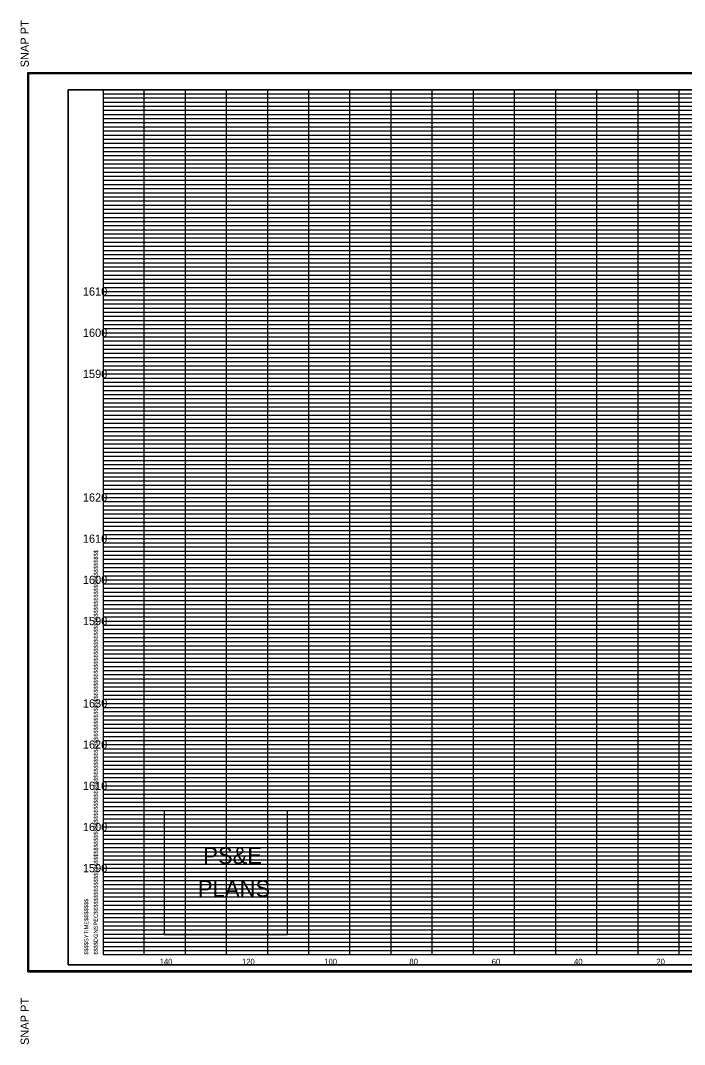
# Model space of a CAD drawing. Extents: x 980 to 1324, y 978 to 1497.
# Drawn here: x 979.9 to 1141.3, y 978.2 to 1226.8 of the extents above; entities that cross this region are included whole.
import ezdxf

# ---------------------------------------------------------------- set-up
doc = ezdxf.new("R2010")
doc.units = 0
for name, color, linetype in [('DESIGN - SHEET - Corner Text', 7, 'Continuous'), ('DESIGN - SHEET - Light Grid', 7, 'Continuous'), ('DESIGN - SHEET - Linework', 7, 'Continuous'), ('DESIGN - SHEET - Plot Shape', 7, 'Continuous'), ('DESIGN - TYPICAL - Text', 7, 'Continuous')]:
    doc.layers.add(name, color=color, linetype=linetype)

# ---------------------------------------------------------------- blocks, each defined once
blk = doc.blocks.new('XSTSHT')
at = {"layer": 'DESIGN - SHEET - Light Grid'}
for p, q in [((0, 20.9), (8, 20.9)), ((8, 20.9), (16, 20.9)), ((0, 20.8), (8, 20.8)), ((0, 20.7), (8, 20.7)), ((8, 20.8), (16, 20.8)), ((8, 20.7), (16, 20.7)), ((0, 20.6), (8, 20.6)), ((0, 20.5), (8, 20.5)), ((0, 20.4), (8, 20.4)), ((8, 20.6), (16, 20.6)), ((8, 20.5), (16, 20.5)), ((8, 20.4), (16, 20.4)), ((0, 20.3), (8, 20.3)), ((0, 20.2), (8, 20.2)), ((8, 20.3), (16, 20.3)), ((8, 20.2), (16, 20.2)), ((0, 20.1), (8, 20.1)), ((0, 19.9), (8, 19.9)), ((8, 20.1), (16, 20.1)), ((8, 19.9), (16, 19.9)), ((0, 19.8), (8, 19.8)), ((0, 19.7), (8, 19.7)), ((8, 19.8), (16, 19.8)), ((8, 19.7), (16, 19.7)), ((0, 19.6), (8, 19.6)), ((0, 19.5), (8, 19.5)), ((0, 19.4), (8, 19.4)), ((8, 19.6), (16, 19.6)), ((8, 19.5), (16, 19.5)), ((8, 19.4), (16, 19.4)), ((0, 19.3), (8, 19.3)), ((0, 19.2), (8, 19.2)), ((8, 19.3), (16, 19.3)), ((8, 19.2), (16, 19.2)), ((0, 19.1), (8, 19.1)), ((0, 18.9), (8, 18.9)), ((8, 19.1), (16, 19.1)), ((8, 18.9), (16, 18.9)), ((0, 18.8), (8, 18.8)), ((0, 18.7), (8, 18.7)), ((8, 18.8), (16, 18.8)), ((8, 18.7), (16, 18.7)), ((0, 18.6), (8, 18.6)), ((0, 18.5), (8, 18.5)), ((0, 18.4), (8, 18.4)), ((8, 18.6), (16, 18.6)), ((8, 18.5), (16, 18.5)), ((8, 18.4), (16, 18.4)), ((0, 18.3), (8, 18.3)), ((0, 18.2), (8, 18.2)), ((8, 18.3), (16, 18.3)), ((8, 18.2), (16, 18.2)), ((0, 18.1), (8, 18.1)), ((8, 18.1), (16, 18.1)), ((0, 17.9), (8, 17.9)), ((0, 17.8), (8, 17.8)), ((0, 17.7), (8, 17.7)), ((8, 17.9), (16, 17.9)), ((8, 17.8), (16, 17.8)), ((8, 17.7), (16, 17.7)), ((0, 17.6), (8, 17.6)), ((0, 17.5), (8, 17.5)), ((8, 17.6), (16, 17.6)), ((8, 17.5), (16, 17.5)), ((0, 17.4), (8, 17.4)), ((0, 17.3), (8, 17.3)), ((0, 17.2), (8, 17.2)), ((8, 17.4), (16, 17.4)), ((8, 17.3), (16, 17.3)), ((8, 17.2), (16, 17.2)), ((0, 17.1), (8, 17.1)), ((8, 17.1), (16, 17.1)), ((0, 16.9), (8, 16.9)), ((0, 16.8), (8, 16.8)), ((0, 16.7), (8, 16.7)), ((8, 16.9), (16, 16.9)), ((8, 16.8), (16, 16.8)), ((8, 16.7), (16, 16.7)), ((0, 16.6), (8, 16.6)), ((0, 16.5), (8, 16.5)), ((8, 16.6), (16, 16.6)), ((8, 16.5), (16, 16.5)), ((0, 16.4), (8, 16.4)), ((0, 16.3), (8, 16.3)), ((0, 16.2), (8, 16.2)), ((8, 16.4), (16, 16.4)), ((8, 16.3), (16, 16.3)), ((8, 16.2), (16, 16.2)), ((0, 16.1), (8, 16.1)), ((8, 16.1), (16, 16.1)), ((0, 15.9), (8, 15.9)), ((0, 15.8), (8, 15.8)), ((0, 15.7), (8, 15.7)), ((8, 15.9), (16, 15.9)), ((8, 15.8), (16, 15.8)), ((8, 15.7), (16, 15.7)), ((0, 15.6), (8, 15.6)), ((0, 15.5), (8, 15.5)), ((8, 15.6), (16, 15.6)), ((8, 15.5), (16, 15.5)), ((0, 15.4), (8, 15.4)), ((0, 15.3), (8, 15.3)), ((0, 15.2), (8, 15.2)), ((8, 15.4), (16, 15.4)), ((8, 15.3), (16, 15.3)), ((8, 15.2), (16, 15.2)), ((0, 15.1), (8, 15.1)), ((8, 15.1), (16, 15.1)), ((0, 14.9), (8, 14.9)), ((0, 14.8), (8, 14.8)), ((0, 14.7), (8, 14.7)), ((8, 14.9), (16, 14.9)), ((8, 14.8), (16, 14.8)), ((8, 14.7), (16, 14.7)), ((0, 14.6), (8, 14.6)), ((0, 14.5), (8, 14.5)), ((8, 14.6), (16, 14.6)), ((8, 14.5), (16, 14.5)), ((0, 14.4), (8, 14.4)), ((0, 14.3), (8, 14.3)), ((0, 14.2), (8, 14.2)), ((8, 14.4), (16, 14.4)), ((8, 14.3), (16, 14.3)), ((8, 14.2), (16, 14.2)), ((0, 14.1), (8, 14.1)), ((8, 14.1), (16, 14.1)), ((0, 13.9), (8, 13.9)), ((0, 13.8), (8, 13.8)), ((0, 13.7), (8, 13.7)), ((8, 13.9), (16, 13.9)), ((8, 13.8), (16, 13.8)), ((8, 13.7), (16, 13.7)), ((0, 13.6), (8, 13.6)), ((0, 13.5), (8, 13.5)), ((8, 13.6), (16, 13.6)), ((8, 13.5), (16, 13.5)), ((0, 13.4), (8, 13.4)), ((0, 13.3), (8, 13.3)), ((0, 13.2), (8, 13.2)), ((8, 13.4), (16, 13.4)), ((8, 13.3), (16, 13.3)), ((8, 13.2), (16, 13.2)), ((0, 13.1), (8, 13.1)), ((8, 13.1), (16, 13.1)), ((0, 12.9), (8, 12.9)), ((0, 12.8), (8, 12.8)), ((0, 12.7), (8, 12.7)), ((8, 12.9), (16, 12.9)), ((8, 12.8), (16, 12.8)), ((8, 12.7), (16, 12.7)), ((0, 12.6), (8, 12.6)), ((0, 12.5), (8, 12.5)), ((8, 12.6), (16, 12.6)), ((8, 12.5), (16, 12.5)), ((0, 12.4), (8, 12.4)), ((0, 12.3), (8, 12.3)), ((0, 12.2), (8, 12.2)), ((8, 12.4), (16, 12.4)), ((8, 12.3), (16, 12.3)), ((8, 12.2), (16, 12.2)), ((0, 12.1), (8, 12.1)), ((8, 12.1), (16, 12.1)), ((0, 11.9), (8, 11.9)), ((0, 11.8), (8, 11.8)), ((0, 11.7), (8, 11.7)), ((8, 11.9), (16, 11.9)), ((8, 11.8), (16, 11.8)), ((8, 11.7), (16, 11.7)), ((0, 11.6), (8, 11.6)), ((0, 11.5), (8, 11.5)), ((8, 11.6), (16, 11.6)), ((8, 11.5), (16, 11.5)), ((0, 11.4), (8, 11.4)), ((0, 11.3), (8, 11.3)), ((0, 11.2), (8, 11.2)), ((8, 11.4), (16, 11.4)), ((8, 11.3), (16, 11.3)), ((8, 11.2), (16, 11.2)), ((0, 11.1), (8, 11.1)), ((8, 11.1), (16, 11.1)), ((0, 10.9), (8, 10.9)), ((0, 10.8), (8, 10.8)), ((0, 10.7), (8, 10.7)), ((8, 10.9), (16, 10.9)), ((8, 10.8), (16, 10.8)), ((8, 10.7), (16, 10.7)), ((0, 10.6), (8, 10.6)), ((0, 10.5), (8, 10.5)), ((8, 10.6), (16, 10.6)), ((8, 10.5), (16, 10.5)), ((0, 10.4), (8, 10.4)), ((0, 10.3), (8, 10.3)), ((0, 10.2), (8, 10.2)), ((8, 10.4), (16, 10.4)), ((8, 10.3), (16, 10.3)), ((8, 10.2), (16, 10.2)), ((0, 10.1), (8, 10.1)), ((8, 10.1), (16, 10.1)), ((0, 9.9), (8, 9.9)), ((0, 9.8), (8, 9.8)), ((0, 9.7), (8, 9.7)), ((8, 9.9), (16, 9.9)), ((8, 9.8), (16, 9.8)), ((8, 9.7), (16, 9.7)), ((0, 9.6), (8, 9.6)), ((0, 9.5), (8, 9.5)), ((8, 9.6), (16, 9.6)), ((8, 9.5), (16, 9.5)), ((0, 9.4), (8, 9.4)), ((0, 9.3), (8, 9.3)), ((0, 9.2), (8, 9.2)), ((8, 9.4), (16, 9.4)), ((8, 9.3), (16, 9.3)), ((8, 9.2), (16, 9.2)), ((0, 9.1), (8, 9.1)), ((8, 9.1), (16, 9.1)), ((0, 8.9), (8, 8.9)), ((0, 8.8), (8, 8.8)), ((8, 8.9), (16, 8.9)), ((8, 8.8), (16, 8.8)), ((0, 8.7), (8, 8.7)), ((0, 8.6), (8, 8.6)), ((0, 8.5), (8, 8.5)), ((8, 8.7), (16, 8.7)), ((8, 8.6), (16, 8.6)), ((8, 8.5), (16, 8.5)), ((0, 8.4), (8, 8.4)), ((0, 8.3), (8, 8.3)), ((8, 8.4), (16, 8.4)), ((8, 8.3), (16, 8.3)), ((0, 8.2), (8, 8.2)), ((0, 8.1), (8, 8.1)), ((8, 8.2), (16, 8.2)), ((8, 8.1), (16, 8.1)), ((0, 7.9), (8, 7.9)), ((0, 7.8), (8, 7.8)), ((8, 7.9), (16, 7.9)), ((8, 7.8), (16, 7.8)), ((0, 7.7), (8, 7.7)), ((0, 7.6), (8, 7.6)), ((0, 7.5), (8, 7.5)), ((8, 7.7), (16, 7.7)), ((8, 7.6), (16, 7.6)), ((8, 7.5), (16, 7.5)), ((0, 7.4), (8, 7.4)), ((0, 7.3), (8, 7.3)), ((8, 7.4), (16, 7.4)), ((8, 7.3), (16, 7.3)), ((0, 7.2), (8, 7.2)), ((0, 7.1), (8, 7.1)), ((8, 7.2), (16, 7.2)), ((8, 7.1), (16, 7.1)), ((0, 6.9), (8, 6.9)), ((0, 6.8), (8, 6.8)), ((8, 6.9), (16, 6.9)), ((8, 6.8), (16, 6.8)), ((0, 6.7), (8, 6.7)), ((0, 6.6), (8, 6.6)), ((0, 6.5), (8, 6.5)), ((8, 6.7), (16, 6.7)), ((8, 6.6), (16, 6.6)), ((8, 6.5), (16, 6.5)), ((0, 6.4), (8, 6.4)), ((0, 6.3), (8, 6.3)), ((8, 6.4), (16, 6.4)), ((8, 6.3), (16, 6.3)), ((0, 6.2), (8, 6.2)), ((0, 6.1), (8, 6.1)), ((8, 6.2), (16, 6.2)), ((8, 6.1), (16, 6.1)), ((0, 5.9), (8, 5.9)), ((0, 5.8), (8, 5.8)), ((8, 5.9), (16, 5.9)), ((8, 5.8), (16, 5.8)), ((0, 5.7), (8, 5.7)), ((0, 5.6), (8, 5.6)), ((0, 5.5), (8, 5.5)), ((8, 5.7), (16, 5.7)), ((8, 5.6), (16, 5.6)), ((8, 5.5), (16, 5.5)), ((0, 5.4), (8, 5.4)), ((0, 5.3), (8, 5.3)), ((8, 5.4), (16, 5.4)), ((8, 5.3), (16, 5.3)), ((0, 5.2), (8, 5.2)), ((0, 5.1), (8, 5.1)), ((8, 5.2), (16, 5.2)), ((8, 5.1), (16, 5.1)), ((0, 4.9), (8, 4.9)), ((0, 4.8), (8, 4.8)), ((8, 4.9), (16, 4.9)), ((8, 4.8), (16, 4.8)), ((0, 4.7), (8, 4.7)), ((0, 4.6), (8, 4.6)), ((0, 4.5), (8, 4.5)), ((8, 4.7), (16, 4.7)), ((8, 4.6), (16, 4.6)), ((8, 4.5), (16, 4.5)), ((0, 4.4), (8, 4.4)), ((0, 4.3), (8, 4.3)), ((8, 4.4), (16, 4.4)), ((8, 4.3), (16, 4.3)), ((0, 4.2), (8, 4.2)), ((0, 4.1), (8, 4.1)), ((8, 4.2), (16, 4.2)), ((8, 4.1), (16, 4.1)), ((0, 3.9), (8, 3.9)), ((0, 3.8), (8, 3.8)), ((8, 3.9), (16, 3.9)), ((8, 3.8), (16, 3.8)), ((0, 3.7), (8, 3.7)), ((0, 3.6), (8, 3.6)), ((0, 3.5), (8, 3.5)), ((8, 3.7), (16, 3.7)), ((8, 3.6), (16, 3.6)), ((8, 3.5), (16, 3.5)), ((0, 3.4), (8, 3.4)), ((0, 3.3), (8, 3.3)), ((8, 3.4), (16, 3.4)), ((8, 3.3), (16, 3.3)), ((0, 3.2), (8, 3.2)), ((0, 3.1), (8, 3.1)), ((8, 3.2), (16, 3.2)), ((8, 3.1), (16, 3.1)), ((0, 2.9), (8, 2.9)), ((0, 2.8), (8, 2.8)), ((8, 2.9), (16, 2.9)), ((8, 2.8), (16, 2.8)), ((0, 2.7), (8, 2.7)), ((0, 2.6), (8, 2.6)), ((0, 2.5), (8, 2.5)), ((8, 2.7), (16, 2.7)), ((8, 2.6), (16, 2.6)), ((8, 2.5), (16, 2.5)), ((0, 2.4), (8, 2.4)), ((0, 2.3), (8, 2.3)), ((8, 2.4), (16, 2.4)), ((8, 2.3), (16, 2.3)), ((0, 2.2), (8, 2.2)), ((0, 2.1), (8, 2.1)), ((8, 2.2), (16, 2.2)), ((8, 2.1), (16, 2.1)), ((0, 1.9), (8, 1.9)), ((0, 1.8), (8, 1.8)), ((8, 1.9), (16, 1.9)), ((8, 1.8), (16, 1.8)), ((0, 1.7), (8, 1.7)), ((0, 1.6), (8, 1.6)), ((0, 1.5), (8, 1.5)), ((8, 1.7), (16, 1.7)), ((8, 1.6), (16, 1.6)), ((8, 1.5), (16, 1.5)), ((0, 1.4), (8, 1.4)), ((0, 1.3), (8, 1.3)), ((8, 1.4), (16, 1.4)), ((8, 1.3), (16, 1.3)), ((0, 1.2), (8, 1.2)), ((0, 1.1), (8, 1.1)), ((8, 1.2), (16, 1.2)), ((8, 1.1), (16, 1.1)), ((0, 0.9), (8, 0.9)), ((0, 0.8), (8, 0.8)), ((8, 0.9), (16, 0.9)), ((8, 0.8), (16, 0.8)), ((0, 0.7), (8, 0.7)), ((0, 0.6), (8, 0.6)), ((0, 0.5), (8, 0.5)), ((8, 0.7), (16, 0.7)), ((8, 0.6), (16, 0.6)), ((8, 0.5), (16, 0.5)), ((0, 0.4), (8, 0.4)), ((0, 0.3), (8, 0.3)), ((8, 0.4), (16, 0.4)), ((8, 0.3), (16, 0.3)), ((0, 0.2), (8, 0.2)), ((0, 0.1), (8, 0.1)), ((8, 0.2), (16, 0.2)), ((8, 0.1), (16, 0.1))]:
    blk.add_line(p, q, dxfattribs=at)
at = {"layer": 'DESIGN - SHEET - Linework'}
for p, q in [((-1.823, -0.414), (-1.823, 21.414)), ((-1.823, 21.414), (32.217, 21.414)), ((1, 0), (1, 21)), ((2, 0), (2, 21)), ((3, 0), (3, 21)), ((4, 0), (4, 21)), ((5, 0), (5, 21)), ((6, 0), (6, 21)), ((7, 0), (7, 21)), ((8, 0), (8, 21)), ((9, 0), (9, 21)), ((10, 0), (10, 21)), ((11, 0), (11, 21)), ((12, 0), (12, 21)), ((13, 0), (13, 21)), ((14, 0), (14, 21)), ((0, 20), (28, 20)), ((0, 19), (32, 19)), ((0, 18), (32, 18)), ((0, 17), (32, 17)), ((0, 16), (32, 16)), ((0, 15), (32, 15)), ((0, 14), (32, 14)), ((0, 13), (32, 13)), ((0, 12), (32, 12)), ((0, 11), (32, 11)), ((0, 10), (32, 10)), ((0, 9), (32, 9)), ((0, 8), (32, 8)), ((0, 7), (32, 7)), ((0, 6), (32, 6)), ((0, 5), (32, 5)), ((0, 4), (32, 4)), ((0, 3), (32, 3)), ((0, 2), (32, 2)), ((0, 1), (32, 1)), ((-1.823, -0.414), (32.217, -0.414))]:
    blk.add_line(p, q, dxfattribs=at)
blk.add_lwpolyline([(0, 21), (0, 0), (32, 0), (32, 21), (0, 21)], dxfattribs=at)
at = {"layer": 'DESIGN - SHEET - Plot Shape'}
for points in [[(-1.803, 21.394), (32.197, 21.394), (32.197, -0.394), (-1.803, -0.394)], [(-0.85, 21), (32, 21), (32, -0.25), (-0.85, -0.25)]]:
    blk.add_lwpolyline(points, close=True, dxfattribs=at)
at = {"layer": 'DESIGN - SHEET - Corner Text'}
for s, height, p in [('  SNAP PT', 0.2, (-1.803, 21.394)), ('$$$$DGNSPEC$$$$$$$$$$$$$$$$$$$$$$$$$$$$$$$$$$$$$$$$$$$$$$$$$$$$$$$$$$$$$$$$$$$$$$$$$$$$$$$$$$$$$$$$$$$$$$$$$$$$$$$$$$$$$$$$$$$', 0.100002, (-0.126, 0)), ('$$$$SYTIME$$$$$$$', 0.1, (-0.358, 0)), ('SNAP PT  ', 0.2, (-1.803, -2.194))]:
    blk.add_text(s, height=height, rotation=90, dxfattribs=at).set_placement(p)

msp = doc.modelspace()

# ---------------------------------------------------------------- linework, layer by layer
at = {"layer": 'DESIGN - SHEET - Corner Text'}
msp.add_lwpolyline([(1014.83, 1034.89), (1014.83, 1004.89), (1044.83, 1004.89), (1044.83, 1034.89)], close=True, dxfattribs=at)
at = {"layer": 'DESIGN - SHEET - Plot Shape'}
msp.add_lwpolyline([(991.5, 997.5), (1320, 997.5), (1320, 1210), (991.5, 1210)], close=True, dxfattribs=at)

# ---------------------------------------------------------------- block references
at = {"layer": 'DESIGN - TYPICAL - Text', "xscale": 10, "yscale": 10}
msp.add_blockref('XSTSHT', (1000, 1000), dxfattribs=at)

# ---------------------------------------------------------------- texts
at = {"layer": 'DESIGN - SHEET - Corner Text'}
for s, p in [('PS&E', (1024.35, 1022.06)), ('PLANS', (1023.06, 1014.06))]:
    msp.add_text(s, height=4, dxfattribs=at).set_placement(p)
at = {"layer": 'DESIGN - TYPICAL - Text'}
for s, height, p in [('     1610     ', 2, (991.37, 1160)), ('     1600     ', 2, (991.37, 1150)), ('     1590     ', 2, (991.37, 1140)), ('     1620     ', 2, (991.37, 1110)), ('     1610     ', 2, (991.37, 1100)), ('     1600     ', 2, (991.37, 1090)), ('     1590     ', 2, (991.37, 1080)), ('     1630     ', 2, (991.37, 1060)), ('     1620     ', 2, (991.37, 1050)), ('     1610     ', 2, (991.37, 1040)), ('     1600     ', 2, (991.37, 1030)), ('     1590     ', 2, (991.37, 1020)), ('     140     ', 1.4, (1011.14, 997.6)), ('     120     ', 1.4, (1031.14, 997.6)), ('     100     ', 1.4, (1051.14, 997.6)), ('     80     ', 1.4, (1071.82, 997.6)), ('     60     ', 1.4, (1091.82, 997.6)), ('     40     ', 1.4, (1111.82, 997.6)), ('     20     ', 1.4, (1131.82, 997.6))]:
    msp.add_text(s, height=height, dxfattribs=at).set_placement(p)

doc.saveas('drawing.dxf')
